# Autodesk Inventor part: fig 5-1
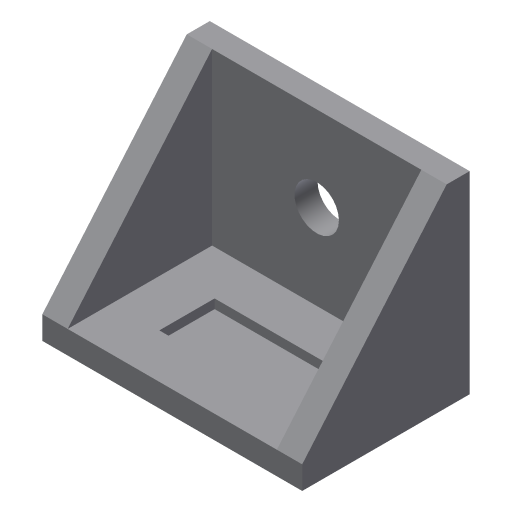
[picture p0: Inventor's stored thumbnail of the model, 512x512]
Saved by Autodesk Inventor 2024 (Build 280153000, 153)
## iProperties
Created: 2012-08
Part Number: fig 5-1
Material: Generic
Document SubType Name: Modeling
Designer: CADCIM
Density: 1 g/cm^3
Appearance: Default
Author: CADCIM
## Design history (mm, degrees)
sketch "Sketch1"
  geometry: L1 (-14.1, 7.837)-(14.1, 7.837); L2 (14.1, 7.837)-(14.1, -7.837); L3 (14.1, -7.837)-(-14.1, -7.837); L4 (-14.1, -7.837)-(-14.1, 7.837); L5 (-14.1, 7.837)-(14.1, -7.837); L6 (14.1, 7.837)-(-14.1, -7.837); 1 further point
  constraints: 12 end point, 2 midpoint, 2 parallel, 1 horizontal, 1 perpendicular
extrude "Extrusion1" new body sketch "Sketch1" distance "d0" = 2.5; taper "d1" = 0 deg
sketch "Sketch2"
  geometry: L1 (0, -20.969)-(28.201, -20.969); L2 (28.201, -20.969)-(28.201, 0); L3 (28.201, 0)-(0, 0); L4 (0, 0)-(0, -20.969); L5 (0, -20.969)-(28.201, 0); L6 (28.201, -20.969)-(0, 0); 1 further point
  constraints: 12 end point, 2 midpoint, 2 parallel, 1 horizontal, 1 perpendicular
extrude "Extrusion2" join sketch "Sketch2" distance "d2" = 2.5; taper "d3" = 0 deg
sketch "Sketch3"
  geometry: L1 (-6.24, 3)-(6.24, 3); L2 (6.24, 3)-(6.24, -3); L3 (6.24, -3)-(-6.24, -3); L4 (-6.24, -3)-(-6.24, 3); L5 (-6.24, 3)-(6.24, -3); L6 (6.24, 3)-(-6.24, -3); 1 further point
  constraints: 12 end point, 2 midpoint, 2 parallel, 1 horizontal, 1 perpendicular
extrude "Extrusion3" cut sketch "Sketch3" distance "d4" = 1; taper "d5" = 0 deg
sketch "Sketch4"
  geometry: L1 (2.5, 18.174)-(2.5, 0) reference; L2 (-18.469, 15.674)-(0, 15.674) reference; L3 (-18.469, 15.674)-(0, 0); L4 (-18.469, 15.674)-(0, 15.674); L5 (0, 0)-(0, 15.674)
  constraints: 6 end point, 1 collinear, 1 parallel
extrude "Extrusion4" join sketch "Sketch4" distance "d6" = 2.75; taper "d7" = 0 deg
mirror "Mirror1"
sketch "Sketch5"
  geometry: C1 r 2.409 at (14.1, 11.735)
  constraints: 1 centre point
extrude "Extrusion5" cut sketch "Sketch5" distance "d8" = 2.75; taper "d9" = 0 deg
body "Solid1"
